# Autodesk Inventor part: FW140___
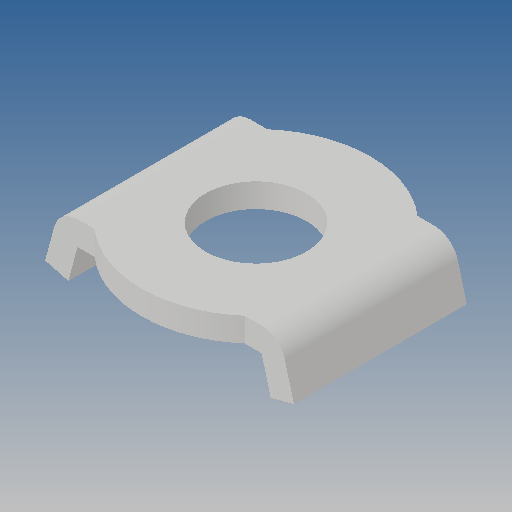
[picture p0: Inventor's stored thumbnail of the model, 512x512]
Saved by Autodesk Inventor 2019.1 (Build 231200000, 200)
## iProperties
Created: 2010-06
Part Number: FW140___
Material: Ogólny
Document SubType Name: Modeling
Designer: CADENGINEERING4
Density: 1 g/cm^3
Appearance: Domyślna
Author: CADENGINEERING4
Revision Number: ANY
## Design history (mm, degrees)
feature "NONE"
node "Bryła1"
